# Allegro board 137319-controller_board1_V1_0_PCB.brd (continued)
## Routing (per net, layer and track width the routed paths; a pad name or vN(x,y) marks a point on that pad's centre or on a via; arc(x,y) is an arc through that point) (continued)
VBUS: length 25.2
  TOP w0.508: v2(13.82,42.04) 13.21,42.04 13.08,42.16 U10.5
  TOP w0.635: v2(9.91,48.39) 9.91,49.6 C89.1
  ART03 w0.635: J5.1 8.86,43.05 11.94,43.05 12.95,42.04 v2(13.82,42.04) v2(13.82,43.03) 13.82,44.09 13.08,44.83 10.79,44.83 9.91,45.72 v2(9.91,47.37) v2(9.91,48.39)
  BOTTOM w0.635: FB4.1 v2(9.91,47.37) v2(9.91,48.39)
VCC: length 16.2
  TOP w0.381: C2.1 v2(51.05,69.47)
  ART03 w0.381: v2(13.72,48.9) 13.72,45.47 14.73,44.45 14.73,39.75 13.34,38.35 v2(13.34,37.34)
  BOTTOM w0.508: U9.2 C90.1 v2(13.34,37.34)
  vias: v2(11.94,81.92) v2(11.94,81.15) v2(12.95,81.92) v2(12.95,81.15) v2(14.61,48.9)
VCC_1V1: length 9.4
  TOP w0.381: U2.V12 33.84,45.05 v1(34.24,44.65) ; v2(33.27,39.62) 34.16,39.62 34.54,39.24 C61.1
  BOTTOM w0.381: v1(34.24,44.65) 34.24,40.59 v2(33.27,39.62) 33.27,39.12 C62.1
VCC_2V5_SDRAM: length 18.4
  TOP w0.381: U2.E6 v1(28.64,55.85) ; v1(31.84,55.85) 32.24,55.46 U2.E10 ; U2.J5 v1(27.84,52.65) ; U2.T11 v1(33.44,46.25)
  TOP w0.508: C45.1 20.19,58.42 C47.1 v2(21.46,59.56)
  ART03 w0.381: v1(31.84,55.85) 32.64,55.06 32.64,47.05 v1(33.44,46.25)
  BOTTOM w0.381: C46.1 32.92,46.25 v1(33.44,46.25) ; v1(28.64,55.85) 28.64,55.05 C44.1 ; C59.1 32.28,55.85 v1(31.84,55.85)
VCC_3V3_ADC: length 10.2
  TOP w0.381: FB2.1 C86.1 20.45,47.37 v2(21.21,47.37) 21.88,46.7 21.88,46.06 22.89,45.05 U2.V1
  BOTTOM w0.381: C85.1 19.68,47.37 v2(21.21,47.37)
VCC_3V3_MCULDO: length 6.6
  TOP w0.381: U2.Y10 32.24,42.14 30.73,40.64 v2(30.73,39.62) C83.1
  BOTTOM w0.381: v2(30.73,39.62) C82.1
VDD12: length 25.9
  TOP w0.381: U2.M8 30.64,49.85 v1(30.24,49.45) ; v1(30.24,47.85) 30.64,48.25 U2.P8 ; v1(31.04,48.65) 31.44,49.05 U2.N9 ; U2.H12 33.84,53.05 v1(34.24,53.45) ; v1(35.04,52.65) 34.64,52.25 U2.J13 ; U2.G9 v1(31.04,54.25) ; U2.L7 29.84,50.65 v1(29.44,50.25) ; U2.K14 35.44,51.45 v1(35.84,51.85) ; U2.P12 v1(34.24,47.85) ; U2.K8 30.64,51.45 v1(30.24,51.85) ; U2.H10 v1(31.84,53.45) ; U2.P14 v1(35.84,47.85) ; v1(31.84,47.85) 32.24,48.25 U2.P10 ; U2.N13 v1(35.04,48.65) ; U2.G7 v1(29.44,54.25) ; U2.L13 34.64,50.65 v1(35.04,50.25) ; U2.N7 29.84,49.05 v1(29.44,48.65) ; U2.H14 35.44,53.05 v1(35.84,53.45) ; v1(35.04,54.25) 34.64,53.85 U2.G13 ; U2.H8 v1(30.24,53.45) ; U2.J7 v1(29.44,52.65) ; U2.N11 v1(33.44,48.65) ; U2.M14 v1(35.84,49.45) ; U2.G11 v1(33.44,54.25)
  BOTTOM w0.381: C57.1 30.24,51.42 v1(30.24,51.85) ; v1(29.44,48.65) 28.79,48.01 C53.1 ; C50.1 35.04,50.81 v1(35.04,50.25) ; C52.1 36.54,51.85 v1(35.84,51.85) ; v1(35.84,47.85) 36.08,47.61 36.08,47.57 36.19,47.46 36.23,47.46 36.45,47.24 C49.1 ; C56.1 32.27,53.45 v1(31.84,53.45) ; v1(34.24,47.85) 34.24,47.17 C55.1 ; C51.1 36.5,49.45 v1(35.84,49.45) ; v1(31.84,47.85) 32.23,47.85 C58.1 ; v2(21.09,53.21) 21.53,53.21 C48.1 21.85,52.4 v2(21.08,52.4) ; C60.1 30.86,47.29 30.3,47.85 v1(30.24,47.85) ; 36.58,53.98 36.36,53.98 v1(35.84,53.45)
VDD15: length 75.3
  TOP w0.254: v2(9.53,72.64) 10.16,73.27 U14.14
  TOP w0.381: C79.1 v2(17.08,65.09) ; U3.R1 v1(32.9,67.65) 33.24,67.31 35.56,67.31 36.32,68.07 37.63,68.07 38.73,66.97 39.88,66.97 40.17,66.67 40.17,65.3 C38.1 ; U2.E9 v1(31.04,55.85) ; U2.D5 v1(27.84,56.65) ; U3.K8 v1(28.9,73.25) ; U2.E7 v1(29.44,55.85) ; U3.D2 v1(24.11,69.25) ; U3.A1 v1(21.71,67.65) ; U2.E4 v1(27.84,55.05) U2.F5 ; U2.D11 v1(33.44,56.65) ; U3.C1 v1(23.31,67.65) ; U3.A8 v1(20.91,74.05) ; U3.E9 v1(24.9,74.05) ; U3.R9 v1(32.9,74.05) ; U2.H5 v1(27.84,53.45) ; U3.N9 v1(31.3,74.05) ; U3.F1 v1(25.71,67.65) ; U3.H2 v1(26.5,69.25) ; U3.K2 v1(28.9,69.25) ; U3.G7 v1(25.71,72.45) ; U3.D9 v1(24.11,74.05) ; U3.N1 30.9,68.05 v1(30.51,67.65) ; U2.K5 v1(27.84,51.85) ; U3.H9 v1(27.3,74.05) ; U3.C9 v1(23.31,74.05) ; U3.B2 v1(22.51,68.45)
  ART03 w0.381: v1(27.84,51.85) 28.36,52.38 28.36,52.93 v1(27.84,53.45)
  BOTTOM w0.305: C39.1 28.07,51.63 v1(27.84,51.85)
  BOTTOM w0.381: C41.1 34.02,56.65 v1(33.44,56.65) ; C16.1 20.91,74.88 v1(20.91,74.05) 20.33,74.05 20.07,73.79 ; v1(28.9,69.25) 29.56,69.25 C24.1 ; R11.1 32.51,67.25 v1(32.9,67.65) ; C42.1 C39.1 ; v1(24.9,74.05) 25.4,74.54 C18.1 ; 23.75,66.67 23.75,67.2 v1(23.31,67.65) ; C40.1 27.95,53.34 v1(27.84,53.45) ; C7.1 23.37,74.11 v1(23.31,74.05) ; v1(25.71,72.45) 25.71,71.93 C22.1 ; C43.1 30.86,55.67 v1(31.04,55.85) ; v1(24.11,69.25) 24.35,69.25 C17.1 ; C12.1 C10.1 32.9,75.07 v1(32.9,74.05) ; v2(17.08,65.09) 17.97,65.09 18.8,64.26 R8.1 C3.1 ; C8.1 21.46,67.4 v1(21.71,67.65) 21.28,68.07 C13.1 ; v2(9.53,72.64) 10.54,71.63 R87.2 11.68,69.6 12.95,68.33 14.48,68.33 15.49,67.31 v2(15.49,66.8) ; C21.1 C19.1 30.61,67.55 v1(30.51,67.65) ; C11.1 C9.1 27.3,75.06 v1(27.3,74.05) ; C14.1 24.11,74.91 v1(24.11,74.05) ; v1(28.9,73.25) 28.75,73.41 C20.1 ; v2(17.02,66.8) 17.4,67.18 17.4,70.36 R88.1
  vias: v2(14.61,66.8) v2(15.82,51.94) v2(17.01,51.94)
VDD33: length 139.2
  TOP w0.127: U2.V8 30.64,45.05 v1(30.24,44.65)
  TOP w0.254: RA4.1 46.23,55.24 46.86,54.61 v2(47.62,54.61) ; RA4.3 v2(47.62,56.26) ; RA3.1 46.74,49.66 v2(46.86,49.53) ; RA7.3 18.29,54.61 v2(17.91,54.23) 18.03,54.1 RA7.4 ; RA7.2 18.16,55.12 v2(17.91,55.37)
  TOP w0.305: v2(17.91,55.37) 18.16,55.63 RA7.1 ; 49.53,24.76 U16.20
  TOP w0.381: v1(35.84,57.45) 36.24,57.06 U2.C15 ; U11.H7 v1(31.35,18.74) ; v1(34.24,57.45) 33.84,57.05 U2.C12 ; U2.W18 38.64,44.25 v1(39.04,43.85) ; C63.1 v2(17.27,37.47) ; U4.J6 v1(43.09,69.86) ; U11.G8 v1(32.95,20.34) ; R80.1 R82.1 27.3,30.73 v2(27.18,30.86) ; v1(38.24,46.25) 37.84,46.65 U2.T17 U2.U16 ; U11.L7 v1(31.35,16.34) U11.L6 ; R54.1 v2(19.75,15.69) ; U2.C18 38.64,57.05 v1(39.04,57.45) ; U11.C7 v1(31.35,23.54) U11.C6 ; U18.5 20.77,33.21 v2(20.83,33.15) ; U11.F7 v1(31.35,21.14) ; U2.T12 33.84,46.65 v1(34.24,46.25) ; D4.2 17.72,39.05 v2(16.89,39.88) ; v1(26.24,48.65) 26.64,49.05 U2.N3 ; U11.G11 v1(34.55,20.34) ; C75.1 v2(44.83,39.62) ; v1(26.24,51.85) 26.64,51.45 U2.K3 ; U4.H8 44.29,71.06 v1(44.69,71.46) ; U11.F11 v1(34.55,21.14) ; v1(38.24,48.65) 37.84,49.05 U2.N17 ; v1(38.24,51.85) 37.84,51.45 U2.K17 ; U11.H11 v1(35.35,18.74) ; U8.4 v2(16.32,26.1) ; R47.2 v2(13.72,30.35) ; U11.C8 v1(32.95,23.54) ; U4.G4 41.09,71.86 v1(40.69,72.26) ; R53.1 v2(17.85,15.69) ; U4.D3 v1(40.69,74.66) ; U11.L8 v1(32.95,16.34) ; U11.G6 v1(30.55,20.34) ; U11.J3 v1(28.15,17.94) ; U11.G3 v1(28.15,20.34) ; R79.1 v2(26.04,30.86) ; U2.F18 38.64,54.65 v1(39.04,55.05) ; U11.F2 v1(27.35,21.14) ; R70.2 v2(45.97,14.35) ; U11.K3 v1(28.15,17.14) ; U2.V14 v1(35.84,44.65) ; U11.J11 v1(35.35,17.94) ; v2(34,30.86) 34,30.82 33.91,30.73 R81.1 ; U2.P5 v1(27.84,48.65) ; D2.2 v2(22.04,35.5) ; R27.2 v2(17.78,56.77)
  TOP w0.508: D3.2 v2(16.95,42.22) ; R85.1 v2(46.35,21.59) ; R84.1 v2(48.64,21.59) ; FB3.2 v2(17.27,46.35) ; S1.9 v2(55.56,42.29) ; FB5.2 v2(41.27,16.13) ; v2(17.27,49.65) 17.27,49.66 FB2.2 ; S1.12 v2(55.56,46.1) ; 56.67,44.83 v2(55.56,44.83) ; R48.2 v2(44.07,59.18) ; 56.67,47.37 v2(55.56,47.37) ; R49.2 v2(44.07,57.91) ; U17.5 v2(41.09,14.41) ; S1.14 v2(55.56,48.64) ; S1.10 v2(55.56,43.56) ; 56.67,49.91 v2(55.56,49.91) ; 49.53,24.76 49.66,24.64 49.66,23.5 v2(50.42,23.5) ; S1.16 v2(55.56,51.18) ; v2(8.51,21.08) 7.75,21.08 7.74,21.08 CN1.4
  BOTTOM w0.305: U15.20 14.36,62.36 v2(14.99,62.99)
  BOTTOM w0.381: v1(35.35,17.94) 35.43,17.86 C107.1 ; C100.1 28.15,19.26 v1(28.15,17.94) ; v2(47.62,56.26) 46.48,56.26 R1.2 ; v2(42.04,62.48) C76.1 C65.1 C69.1 ; C97.1 34.66,20.45 v1(34.55,20.34) ; C72.1 36.65,57.45 v1(35.84,57.45) ; C27.1 45.3,71.46 v1(44.69,71.46) ; v1(40.69,72.26) 40.69,72.44 C28.1 ; v1(39.04,43.85) 38.86,43.68 C64.1 ; R29.1 33.91,35.73 v2(33.74,35.56) ; v1(28.15,20.34) 28.72,20.34 C96.1 ; v2(16.88,22.86) 16.88,21.1 17.27,20.7 R56.1 ; v1(32.95,20.34) 32.95,19.87 C99.1 ; v1(32.95,23.54) 33.36,23.54 C106.1 ; v1(35.84,44.65) 35.43,44.25 C67.1 ; v2(17.27,46.35) 17.4,46.23 R46.1 ; v2(46.86,49.53) 45.97,50.42 R5.2 ; v1(39.04,55.05) 38.09,56.01 C71.1 ; R33.1 R35.1 ; C109.1 35.43,18.82 v1(35.35,18.74) ; C88.2 v2(8.51,21.08) ; C25.1 40.69,74.5 v1(40.69,74.66) 40.12,74.66 39.5,74.04 38.99,74.04 ; C98.1 27.76,17.53 v1(28.15,17.14) ; v2(15.75,30.48) 16.51,30.48 17.78,31.75 R50.2 ; R2.2 46.86,54.61 v2(47.62,54.61) ; v2(47.73,51.06) 47.73,51.56 47.48,51.82 46.74,51.82 R4.2 R3.2 ; v1(43.09,69.86) 42.93,69.7 C26.1 ; R58.1 v2(16.32,26.1) ; R57.1 18.8,23.94 v2(18.8,22.86) ; v1(39.04,57.45) 39.12,57.53 C66.1 ; R75.2 v2(31.37,30.86) ; C108.1 32.34,16.34 v1(32.95,16.34) ; v2(42.8,36.83) 42.04,37.59 42.04,37.72 ; v1(38.24,46.25) 39.03,45.47 C68.1 ; R71.2 42.93,11.18 43.31,10.79 v2(43.31,9.27) ; 43.31,12.32 v2(44.07,12.32) ; R55.1 v2(20.7,20.7) ; 39.75,37.72 v2(39.75,36.83) ; C36.1 v2(20.83,33.15)
  BOTTOM w0.508: v2(41.09,14.41) 41.15,14.35 C93.1 ; C74.1 C70.1 v2(40.26,76.16) ; v2(8.51,22.86) 7.75,22.86 C87.1 ; v2(17.27,49.65) 17.52,49.4 R35.1 ; C1.1 v2(14.99,62.99) ; R16.1 v2(42.55,78.87) ; C73.1 v2(41.27,76.16) ; R17.1 v2(44.2,78.87)
  vias: v2(23.88,30.86) v2(24,22.23) v2(24,21.34) v2(24.89,30.86) v2(24.94,12.7) v2(24.94,11.81) v2(56.01,59.69) v2(56.01,58.8)
AD0: length 62.8
  ART03 w0.127: v2(18.03,40.01) 18.29,39.75 18.29,32.51 21.08,29.72 21.08,27.24 22.48,25.85 22.48,12.57 v2(21.34,11.43)
  BOTTOM w0.152: R38.2 18.16,39.88 v2(18.03,40.01) ; v2(21.34,11.43) 21.34,11.3 26.04,6.6 46.4,6.6 J2.39
AD1: length 67.6
  ART03 w0.127: v2(21.34,10.29) 22.86,11.81 22.86,26 21.46,27.4 21.46,35.43 20.19,36.7 20.19,43.43 v2(21.21,44.45)
  BOTTOM w0.152: v2(21.34,10.29) 25.53,6.1 44.9,6.1 J2.37 ; R39.2 19.05,43.81 19.68,44.45 v2(21.21,44.45)
AD2: length 55.5
  ART03 w0.127: v2(21.34,9.14) 23.24,11.05 23.24,26.16 22.1,27.3 v2(22.1,33.15)
  BOTTOM w0.152: v2(21.34,9.14) 24.89,5.59 43.41,5.59 J2.35 ; v2(22.1,33.15) 21.97,33.15 21.08,34.04 R40.2
BCTRL: length 9.4
  TOP w0.127: 22.86,46.1 22.99,45.97 24.26,45.97 24.53,46.25 25.43,46.25 U2.T2
  TOP w0.152: 22.86,46.1 22.48,46.48 22.48,48.77 20.26,50.99 Q1.1
BOARD_ID0: length 10.1
  TOP w0.127: v1(36.64,46.25) 36.24,46.65 U2.T15
  BOTTOM w0.127: v1(36.64,46.25) 36.24,45.86 36.24,42.42
  BOTTOM w0.152: R29.2 R30.1 36.24,39.67 36.24,42.42
BOARD_ID1: length 11
  TOP w0.127: U2.U15 36.24,45.85 v1(36.64,45.45)
  BOTTOM w0.152: v1(36.64,45.45) 37.05,45.05 37.05,41.18 38.73,39.5 40.13,39.5 R32.1 R31.2
BOARD_ID2: length 10.3
  TOP w0.127: U2.P4 v1(27.04,48.65)
  BOTTOM w0.127: 22.86,48.51 23.12,48.25 26.64,48.25 v1(27.04,48.65)
  BOTTOM w0.152: 22.86,48.51 22.73,48.64 21.46,48.64 R33.2 R34.1
BOARD_ID3: length 8.9
  TOP w0.127: v1(26.24,47.85) 26.64,48.25 U2.P3
  BOTTOM w0.127: 22.86,47.75 23.16,47.46 25.84,47.46 v1(26.24,47.85)
  BOTTOM w0.152: R35.2 R36.1 22.35,48.26 22.86,47.75
BOOT_SEL: length 8.6
  TOP w0.127: U11.D7 v1(31.35,22.74)
  BOTTOM w0.127: v1(31.35,22.74) 31.75,23.14 31.75,26.04
  BOTTOM w0.152: R75.1 R74.2 32.64,27.56 31.75,26.67 31.75,26.04
BOOTMOD0: length 17.3
  TOP w0.127: U2.N18 38.64,49.05 v1(39.04,48.65)
  TOP w0.152: S1.1 v2(51.69,51.18) ; RA1.5 v2(44.07,48.39)
  ART04 w0.127: v2(44.07,48.39) 44.07,49.02 45.47,50.42 50.93,50.42 v2(51.69,51.18)
  BOTTOM w0.127: 41.27,49.05 41.13,49.05 41.12,49.05 39.44,49.05 v1(39.04,48.65)
  BOTTOM w0.152: v2(44.07,48.39) 43.41,49.05 41.27,49.05
BOOTMOD1: length 19.9
  TOP w0.127: U2.N16 v1(37.44,48.65)
  TOP w0.152: RA1.6 44.35,47.88 44.3,47.83 43.36,47.83 v2(42.8,48.39) ; 50.52,49.91 v2(51.69,49.91)
  ART04 w0.127: v2(42.8,48.39) 43.35,47.84 44.4,47.84 46.64,50.08 51.52,50.08 v2(51.69,49.91)
  BOTTOM w0.127: 41.27,48.25 37.84,48.25 v1(37.44,48.65)
  BOTTOM w0.152: v2(42.8,48.39) 42.67,48.25 41.27,48.25
CAN_RX: length 32.3
  TOP w0.127: U2.B14 v1(35.84,58.25)
  ART03 w0.127: v1(35.84,58.25) 35.31,58.79 35.31,59.44 35.94,60.07 35.94,65.28 36.2,65.53 36.2,77.81 J1.18
CAN_TX: length 34.8
  TOP w0.152: v2(38.43,61.59) 37.59,62.43 37.59,64.26 37.34,64.52 R26.1
  BOTTOM w0.152: J1.17 29.01,86.99 29.01,85.59 31.67,82.93 32.26,82.93 37.21,77.98 37.21,67.94 38.43,66.73 v2(38.43,61.59)
CPU_RST_N: length 23.8
  TOP w0.254: R66.1 32.13,30.48 32.13,31.62 v2(31.37,32.38) ; R51.1 C37.1 R47.1 16.85,31.24 U18.3 17.08,31.31 v2(17.91,30.48)
  ART04 w0.254: v2(31.37,32.38) 30.1,33.66 24.13,33.66 22.71,32.23 19.66,32.23 v2(17.91,30.48)
DDR_A0: length 22.5
  TOP w0.127: v1(30.24,57.45) 29.84,57.05 U2.C7 ; U3.N3 v1(30.51,70.05)
  ART03 w0.127: v1(30.51,70.05) 30.1,69.64 30.1,67.28 31.24,66.14 31.24,64.14 31.37,64.01 31.62,64.01 31.75,63.88 31.75,63.63 31.62,63.5 31.37,63.5 31.24,63.37 31.24,63.12 31.37,62.99 33.15,62.99 33.27,62.87 33.27,62.61 33.15,62.48 30.6,62.48 30.48,62.36 30.48,61.9 30.15,61.57 30.15,61.27 29.7,60.82 29.7,60.37 29.84,60.23 29.84,59.65 29.84,59.65 29.84,59.22 29.84,59.22 29.84,58.89 29.84,58.89 29.84,58.8 29.99,58.66 31.5,58.66 31.62,58.53 31.62,58.29 31.5,58.17 30.95,58.17 v1(30.24,57.45)
DDR_A1: length 20.2
  TOP w0.127: U2.C11 v1(33.44,57.45) ; U3.P7 v1(32.11,72.45)
  BOTTOM w0.127: 33.45,72.85 32.51,72.85 v1(32.11,72.45)
  BOTTOM w0.152: 33.45,72.85 35.69,70.61 35.69,64.26 33.53,62.1 33.53,59.31 33.02,58.8 33.02,57.87 v1(33.44,57.45)
DDR_A2: length 21.3
  TOP w0.127: U3.P3 v1(32.11,69.25) ; 30.86,60.2 30.86,60.07 30.64,59.85 U2.A8
  TOP w0.152: v2(31.41,61.09) 30.86,60.54 30.86,60.2
  ART03 w0.127: v1(32.11,69.25) 32.71,69.85 34.29,69.85 34.54,69.6 34.54,61.85 33.53,60.83 33.53,60.58 33.66,60.45 34.1,60.45 34.29,60.26 34.29,60.07 34.16,59.94 33.15,59.94 33.02,60.07 33.02,60.96 32.89,61.09 32.64,61.09 32.51,60.96 32.51,60.71 32.38,60.58 32.13,60.58 32,60.71 32,60.96 31.88,61.09 v2(31.41,61.09)
DDR_A3: length 20.2
  TOP w0.127: U3.N2 v1(31.3,69.25) ; U2.B7 29.44,58.25 29.44,59.02 v1(30.24,59.82)
  ART04 w0.127: v1(31.3,69.25) 31.7,68.85 31.7,67.95 32.73,66.93 33.66,66.93 33.78,66.8 33.78,64.77 33.66,64.64 32.89,64.64 32.77,64.52 32.77,64.26 32.89,64.14 33.66,64.14 33.76,64.03 33.76,63.75 33.63,63.63 32.89,63.63 32.77,63.5 32.77,63.25 32.89,63.12 33.66,63.12 33.78,62.99 33.78,62.74 33.66,62.61 32.89,62.61 32.77,62.48 32.77,60.96 32.27,60.47 30.89,60.47 v1(30.24,59.82)
DDR_A4: length 20.8
  TOP w0.127: U2.A6 29.04,59.52 v1(29.34,59.82) ; U3.P8 v1(32.11,73.25)
  ART04 w0.127: v1(29.34,59.82) 29.3,59.86 29.3,60.52 30.51,61.72 32,61.72 32.38,62.1 32.38,64.9 32.51,65.02 33.27,65.02 33.4,65.15 33.4,66.42 33.27,66.55 32.64,66.55 32.13,67.06 31.11,67.06 30.9,67.27 30.9,70.27 31.71,71.08 31.71,72.85 v1(32.11,73.25)
DDR_A5: length 21.5
  TOP w0.127: 28.7,60.2 28.63,60.13 28.63,58.26 U2.B6 ; U3.P2 v1(31.3,68.45)
  TOP w0.152: v2(30.25,60.6) 29.1,60.6 28.7,60.2
  ART03 w0.127: v1(31.3,68.45) 30.9,68.04 30.9,67.02 31.62,66.29 31.88,66.29 32,66.17 32,65.79 31.88,65.66 31.75,65.66 31.62,65.53 31.62,65.15 31.75,65.02 32.26,65.02 32.38,64.9 32.38,64.64 32.51,64.52 32.77,64.52 32.89,64.64 32.89,65.02 33.02,65.15 33.27,65.15 33.4,65.02 33.4,64.14 33.27,64.01 32.26,64.01 32.13,63.88 32.13,63.63 32.26,63.5 33.53,63.5 33.66,63.37 33.66,62.36 33.4,62.1 31.15,62.1 30.48,61.44 30.48,60.83 v2(30.25,60.6)
DDR_A6: length 20.1
  TOP w0.127: U3.R8 v1(32.9,73.25) ; U2.A9 v1(31.44,59.3)
  ART04 w0.127: v1(32.9,73.25) 34.16,71.99 34.16,62.48 33.91,62.23 33.27,62.23 33.15,62.1 33.15,61.85 33.27,61.72 33.91,61.72 34.04,61.59 34.04,61.34 33.91,61.21 33.27,61.21 33.15,61.09 33.15,59.18 32.88,58.91 31.83,58.91 v1(31.44,59.3)
DDR_A7: length 21.7
  TOP w0.127: U2.A7 29.84,58.65 v1(30.24,59.05) ; U3.R2 v1(32.11,68.45)
  ART03 w0.127: v1(30.24,59.05) 30.86,59.68 30.86,61.35 31.14,61.63 32.98,61.63 33.27,61.34 33.53,61.34 34.16,61.98 34.16,64.52 34.04,64.64 33.91,64.64 33.78,64.77 33.78,65.02 33.91,65.15 34.04,65.15 34.16,65.28 34.16,65.53 34.04,65.66 33.4,65.66 33.27,65.79 33.27,66.04 33.4,66.17 34.04,66.17 34.16,66.29 34.16,67.82 34.04,67.94 33.78,67.94 33.66,67.82 33.66,66.67 33.53,66.55 33.27,66.55 33.15,66.67 33.15,67.06 33.02,67.18 32.77,67.18 32.64,67.06 32.64,66.93 32.51,66.8 31.75,66.8 31.62,66.93 31.62,67.18 31.75,67.31 31.98,67.31 32.11,67.44 v1(32.11,68.45)
DDR_A8: length 19
  TOP w0.127: U2.A11 33.04,59.52 33.72,60.2 ; U3.T8 v1(33.71,73.25)
  TOP w0.152: 33.72,60.2 v1(34.38,60.87)
  BOTTOM w0.152: v1(34.38,60.87) 34.38,62.45 34.92,62.99 35.18,62.99 35.31,62.87 35.31,62.48 35.43,62.36 35.69,62.36 35.81,62.48 35.81,62.99 36.07,63.25 36.07,70.88 v1(33.71,73.25)
DDR_A9: length 18.5
  TOP w0.127: U3.R3 v1(32.9,69.25) ; v1(31.44,60.06) 31.03,59.66 31.03,58.26 U2.B9
  BOTTOM w0.127: 31.3,60.2 v1(31.44,60.06)
  BOTTOM w0.152: v1(32.9,69.25) 33.75,69.25 34.16,68.83 34.16,65.15 33.02,64.01 31.65,64.01 30.48,62.84 30.48,62.48 30.61,62.36 31.37,62.36 31.5,62.23 31.5,61.98 31.37,61.85 30.23,61.85 30.1,61.72 30.1,61.47 30.23,61.34 30.61,61.34 30.81,61.14 30.81,60.7 31.3,60.2
DDR_A10: length 20.4
  TOP w0.127: U3.L7 v1(29.71,72.45) ; U2.D7 v1(29.44,56.65)
  ART04 w0.127: v1(29.44,56.65) 29.04,57.05 29.04,59.55 28.92,59.67 28.92,61.69 29.71,62.48 31.5,62.48 31.62,62.61 31.62,65.41 29.3,67.72 29.3,70.47 29.71,70.87 v1(29.71,72.45)
DDR_A11: length 19.4
  TOP w0.127: U3.R7 v1(32.9,72.45) ; U2.D10 v1(31.84,56.65)
  BOTTOM w0.152: v1(31.84,56.65) 31.84,58.26 33.15,59.56 33.15,62.36 35.31,64.52 35.31,70.05 v1(32.9,72.45)
DDR_A12: length 18.9
  TOP w0.127: v1(32.26,60.07) 32.66,59.67 32.66,59.14 32.65,59.13 32.65,57.46 U2.C10 ; v1(31.3,72.45) U3.N7
  BOTTOM w0.127: 32.26,60.2 v1(32.26,60.07)
  BOTTOM w0.152: v1(31.3,72.45) 31.3,71.95 33.4,69.85 33.91,69.85 34.54,69.22 34.54,64.9 32.26,62.61 32.26,60.2
DDR_BA0: length 22.1
  TOP w0.127: U3.M2 v1(30.51,69.25) ; U2.C8 v1(31.04,57.45)
  ART03 w0.127: v1(30.51,69.25) 31.49,70.23 34.54,70.23 34.92,69.85 34.92,60.2 34.29,59.56 33.27,59.56 32.38,58.67 32.13,58.67 32,58.55 32,58.29 32.13,58.17 32.38,58.17 32.51,58.04 32.51,57.78 32.38,57.66 31.24,57.66 v1(31.04,57.45)
DDR_BA1: length 20
  TOP w0.127: v1(32.26,59.31) 31.84,58.89 31.84,57.45 U2.C9 ; U3.N8 v1(31.3,73.25)
  BOTTOM w0.127: 32.13,71.75 31.71,72.18 31.71,72.43 31.7,72.44 31.7,72.85 v1(31.3,73.25)
  BOTTOM w0.152: v1(32.26,59.31) 32.77,59.82 32.77,62.48 34.92,64.64 34.92,69.47 33.99,70.41 33.48,70.41 32.13,71.75
DDR_BA2: length 22.2
  TOP w0.127: U2.D8 v1(30.24,56.65) ; U3.M3 v1(29.71,70.05)
  ART03 w0.127: v1(30.24,56.65) 29.84,57.05 29.84,57.61 29.46,57.99 29.46,58.17 29.36,58.27 29.07,58.27 28.96,58.39 28.96,58.56 29.07,58.67 29.34,58.67 29.46,58.8 29.46,59.05 29.34,59.18 29.08,59.18 28.96,59.31 28.96,59.44 28.83,59.56 28.83,60.33 28.96,60.45 29.21,60.45 29.34,60.58 29.34,60.83 29.21,60.96 28.96,60.96 28.83,61.09 28.83,61.85 29.08,62.1 29.84,62.1 30.1,62.36 30.1,62.74 30.23,62.87 30.73,62.87 30.86,62.99 30.86,63.25 30.73,63.37 30.23,63.37 30.1,63.5 30.1,64.01 30.23,64.14 30.71,64.14 30.83,64.26 30.83,65.3 30.73,65.41 29.72,65.41 29.59,65.53 29.59,65.77 29.72,65.9 30.48,65.9 30.61,66.03 30.61,66.29 30.48,66.42 29.83,66.42 29.71,66.55 v1(29.71,70.05)
DDR_CAS_B: length 17.9
  TOP w0.127: U2.B4 v1(27.84,58.25) ; U3.K3 v1(28.11,70.05)
  BOTTOM w0.127: v1(28.11,70.05) 28.5,69.65 28.5,68.15
  BOTTOM w0.152: 28.5,68.15 29.1,67.55 29.6,67.55 30.07,67.08 30.07,63.86 28.32,62.1 27.56,62.1 27.43,61.98 27.43,61.59 27.56,61.47 27.94,61.47 28.07,61.34 28.07,61.09 27.94,60.96 27.56,60.96 27.43,60.83 27.43,60.55 27.53,60.45 27.94,60.45 28.07,60.33 28.07,60.07 27.94,59.94 27.43,59.94 27.31,59.82 27.31,58.79 v1(27.84,58.25)
DDR_CKE: length 22.1
  TOP w0.127: U3.K9 v1(28.9,74.05) ; U2.A5 28.24,60.2
  TOP w0.152: 28.24,60.2 28.24,60.24 v2(29.46,61.47)
  ART04 w0.127: v2(29.46,61.47) 30.1,62.1 31.75,62.1 32,62.36 32,66.42 31.75,66.67 30.82,66.67 29.97,67.52 29.97,69.67 30.11,69.8 30.11,70.21 30.1,70.21 30.1,73.42 29.87,73.65 29.3,73.65 v1(28.9,74.05)
  BOTTOM w0.127: R14.1 28.32,74.63 v1(28.9,74.05)
DDR_CLK: length 20.8
  TOP w0.13: U2.A2 25.84,59.42 v1(26.24,59.82) ; U3.J7 v1(28.11,72.45)
  ART04 w0.114: v1(28.11,72.45) 28.32,72.23 28.32,72.02 27.06,70.76 27.06,67.17 27.67,66.56 28.31,66.56 28.45,66.42 28.45,65.66 28.32,65.53 26.66,65.53 26.3,65.18 26.3,64.36 26.94,63.73 26.94,63.32 26.8,63.18 26.8,62.98 26.94,62.84 26.94,62.63 26.8,62.49 26.8,62.29 26.94,62.15 26.94,61.95 26.8,61.81 26.8,61.6 26.94,61.47 26.94,61.26 26.8,61.12 26.8,60.92 26.94,60.78 26.94,60.58 26.8,60.44 26.8,60.23 26.94,60.09 26.94,59.84 26.71,59.62 26.44,59.62 v1(26.24,59.82)
  BOTTOM w0.13: v1(28.11,72.45) 28.36,72.19 28.36,71.96 28,71.59 R10.1
DDR_CLK_B: length 20.9
  TOP w0.13: U2.B2 26.24,58.25 v1(26.24,59.05) ; U3.K7 v1(28.9,72.45)
  ART04 w0.114: v1(26.24,59.05) 26.44,59.25 26.87,59.25 27.3,59.69 27.3,63.88 26.67,64.52 26.67,65.02 26.81,65.16 28.47,65.16 28.82,65.51 28.82,66.57 28.46,66.93 27.83,66.93 27.43,67.32 27.43,70.61 28.69,71.87 28.69,72.23 v1(28.9,72.45)
  BOTTOM w0.13: R10.2 29.01,71.6 28.65,71.96 28.65,72.19 v1(28.9,72.45)
DDR_CS_B: length 19.3
  TOP w0.127: U2.C5 v1(27.84,57.45) ; U3.L2 v1(28.9,68.45)
  ART04 w0.127: v1(27.84,57.45) 28.32,57.94 28.32,58.17 28.45,58.29 28.57,58.29 28.7,58.42 28.7,58.67 28.57,58.8 28.45,58.8 28.32,58.93 28.32,61.85 29.34,62.87 31.11,62.87 31.24,62.99 31.24,63.25 31.11,63.37 30.73,63.37 30.61,63.5 30.61,63.88 30.73,64.01 31.11,64.01 31.24,64.14 31.24,64.39 31.11,64.52 30.1,64.52 29.97,64.64 29.97,64.9 30.1,65.02 30.86,65.02 30.99,65.15 30.99,65.41 30.86,65.53 30.19,65.53 29.97,65.75 29.97,66.55 28.9,67.62 v1(28.9,68.45)
DDR_D0: length 29.3
  TOP w0.127: U2.F4 27.44,54.65 v1(27.04,55.05) ; U3.E3 v1(24.11,70.05)
  ART03 w0.127: v1(27.04,55.05) 26.64,55.45 25.96,55.45 25.66,55.75 25.53,55.75 25.4,55.88 25.27,55.88 25.15,56.01 25.15,56.13 25.02,56.26 24.83,56.26 24.57,56.01 24.38,56.01 24.26,56.13 24.26,56.64 24.13,56.77 23.24,56.77 23.11,56.9 23.11,57.78 22.99,57.91 22.48,57.91 22.35,58.04 22.35,58.29 22.48,58.42 23.11,58.42 23.24,58.55 23.24,58.8 23.11,58.93 22.48,58.93 22.35,59.05 22.35,59.31 22.48,59.44 23.62,59.44 23.75,59.56 23.75,59.82 23.62,59.94 22.48,59.94 21.72,60.71 21.72,62.36 20.95,63.12 20.95,67.18 21.21,67.44 21.21,67.82 20.95,68.07 20.95,68.33 21.34,68.71 21.34,68.96 21.21,69.09 21.08,69.09 20.95,69.22 20.95,69.52 21.08,69.65 22.15,69.65 22.23,69.72 22.23,70.23 22.35,70.36 22.61,70.36 22.73,70.23 22.73,69.77 22.86,69.65 23.71,69.65 v1(24.11,70.05)
DDR_D1: length 29.6
  TOP w0.127: v1(26.24,53.45) 26.64,53.05 U2.H3 ; U3.F7 v1(24.9,72.45)
  ART03 w0.127: v1(26.24,53.45) 25.67,53.45 25.04,54.09 25.04,54.42 24.8,54.65 23.84,54.65 21.84,56.64 21.21,56.64 20.32,57.53 20.32,60.83 19.81,61.34 19.81,70.74 21.08,72.01 21.46,72.01 21.59,71.88 21.59,71.65 21.72,71.53 22,71.53 22.1,71.63 22.1,71.88 22.23,72.01 22.48,72.01 22.61,71.88 22.61,71.63 22.73,71.5 22.99,71.5 23.11,71.63 23.11,71.88 23.24,72.01 24.47,72.01 v1(24.9,72.45)
DDR_D2: length 29.4
  TOP w0.127: U2.D4 v1(27.04,56.65) ; U3.F2 v1(25.71,68.45)
  ART03 w0.127: v1(25.71,68.45) 26.1,68.84 26.79,68.84 26.92,68.71 26.92,66.93 26.67,66.67 26.67,66.42 26.8,66.29 27.56,66.29 27.69,66.17 27.69,65.91 27.56,65.79 27.43,65.79 27.3,65.66 27.3,65.41 27.43,65.28 27.56,65.28 27.69,65.15 27.69,64.9 27.56,64.77 27.42,64.77 27.3,64.66 27.3,64.39 27.43,64.26 27.56,64.26 27.69,64.14 27.69,63.88 27.56,63.75 27.43,63.75 27.3,63.63 27.3,63.37 27.56,63.12 27.56,62.87 27.3,62.61 27.3,62.36 27.18,62.23 26.92,62.23 26.8,62.36 26.8,62.87 26.67,62.99 26.42,62.99 26.29,62.87 26.29,62.36 26.16,62.23 25.91,62.23 25.78,62.36 25.78,62.87 25.65,62.99 25.4,62.99 25.27,62.87 25.27,61.98 25.4,61.85 27.18,61.85 27.3,61.72 27.3,61.47 27.18,61.34 27.05,61.34 26.92,61.21 26.92,60.96 27.05,60.83 27.19,60.83 27.3,60.72 27.3,59.8 27.18,59.67 27.18,58.8 27.05,58.67 26.8,58.67 26.67,58.8 26.67,60.45 26.54,60.58 25.91,60.58 25.78,60.45 25.78,58.84 26.18,58.44 26.18,58.02 26.29,57.91 26.51,57.91 26.64,57.78 26.64,57.05 v1(27.04,56.65)
DDR_D3: length 30.3
  TOP w0.127: U2.G4 v1(27.84,54.25) ; U3.F8 v1(25.71,73.25)
  ART03 w0.127: v1(27.84,54.25) 27.6,54.25 27.2,53.85 26.03,53.85 25.84,54.04 25.84,54.42 25.6,54.65 25.27,54.65 24.93,54.99 24,54.99 21.97,57.02 21.34,57.02 20.7,57.66 20.7,61.09 20.15,61.63 20.15,70.07 21.21,71.12 23.37,71.12 23.88,71.63 25.02,71.63 25.31,71.91 25.31,72.85 v1(25.71,73.25)
DDR_D4: length 29.7
  TOP w0.127: U3.H3 v1(26.51,70.05) ; U2.F3 v1(27.04,54.25)
  ART03 w0.127: v1(27.04,54.25) 27.44,54.65 27.44,57.78 27.31,57.91 27.04,57.91 26.92,58.02 26.92,58.18 27.04,58.29 27.3,58.29 27.44,58.43 27.44,59.31 27.69,59.56 27.69,62.48 28.07,62.87 28.07,66.17 28.19,66.29 28.45,66.29 28.57,66.42 28.57,66.67 28.45,66.8 28.07,66.8 27.94,66.67 27.43,66.67 27.33,66.78 27.33,67.08 27.56,67.31 27.56,67.56 27.3,67.82 27.3,68.2 27.56,68.45 27.56,68.71 27.3,68.96 27.3,69.22 27.56,69.47 27.56,70.36 27.69,70.48 28.07,70.48 28.19,70.61 28.19,70.87 28.07,70.99 27.05,70.99 26.92,71.12 26.92,71.37 27.05,71.5 27.94,71.5 28.07,71.63 28.07,71.88 27.94,72.01 27.68,72.01 27.56,72.13 27.56,72.77 27.43,72.9 27.18,72.9 27.05,72.77 27.05,72.14 26.92,72.01 26.67,72.01 26.51,71.84 v1(26.51,70.05)
DDR_D5: length 29.6
  TOP w0.127: U3.H8 26.9,73.65 v1(26.51,73.25) ; U2.J3 v1(27.04,51.85)
  ART03 w0.127: v1(27.04,51.85) 27.44,52.25 27.44,53.6 27.44,53.61 27.44,53.62 27.68,53.85 27.69,53.85 27.7,53.86 28,53.86 28.24,54.09 28.24,58.89 28.24,59.39 28.06,59.56 28.06,62.35 28.45,62.74 28.45,65.66 28.96,66.17 28.96,66.8 28.5,67.26 28.5,70.36 28.63,70.48 29.59,70.48 29.72,70.61 29.72,70.87 29.59,70.99 28.96,70.99 28.83,71.12 28.83,71.37 28.96,71.5 29.72,71.5 29.84,71.63 29.84,71.88 29.72,72.01 28.63,72.01 28.5,72.14 28.5,73.1 28.35,73.25 v1(26.51,73.25)
DDR_D6: length 29.9
  TOP w0.127: v1(26.24,56.65) 26.64,57.05 U2.C3 ; U3.G2 v1(25.71,69.25)
  ART03 w0.127: v1(25.71,69.25) 25.31,68.85 25.31,66 25.4,65.91 25.65,65.91 25.78,66.04 25.78,67.16 25.93,67.31 26.16,67.31 26.29,67.18 26.29,66.04 26.42,65.91 26.8,65.91 26.92,65.79 26.92,65.53 26.8,65.41 25.02,65.41 24.89,65.28 24.89,65.02 25.02,64.9 26.8,64.9 26.92,64.77 26.92,64.52 26.8,64.39 25.02,64.39 24.89,64.26 24.89,64.01 25.02,63.88 26.8,63.88 26.92,63.75 26.92,63.5 26.8,63.37 25.02,63.37 24.89,63.25 24.89,61.59 25.02,61.47 26.42,61.47 26.54,61.34 26.54,61.09 26.42,60.96 25.78,60.96 25.45,60.63 25.45,58.8 25.84,58.41 25.84,57.05 v1(26.24,56.65)
DDR_D7: length 29.9
  TOP w0.127: U2.G3 26.64,53.85 v1(26.24,54.25) ; U3.H7 v1(26.51,72.45)
  ART03 w0.127: v1(26.51,72.45) 26.16,72.1 26.16,70.74 26.04,70.61 25.78,70.61 25.65,70.74 25.65,71.12 25.53,71.25 25.27,71.25 25.15,71.12 25.15,70.74 25.02,70.61 24.77,70.61 24.64,70.74 24.64,71.12 24.51,71.25 24.26,71.25 24.13,71.12 24.13,70.87 24,70.74 21.46,70.74 20.57,69.85 20.57,62.99 21.34,62.23 21.34,60.33 21.46,60.2 21.76,60.2 22.01,59.95 22.01,57.45 23.96,55.5 25.56,55.5 25.84,55.22 25.84,54.93 25.84,54.93 25.84,54.89 26.24,54.49 v1(26.24,54.25)
DDR_D8: length 29.1
  TOP w0.127: U2.J1 25.04,52.25 v1(24.64,52.65)
  TOP w0.381: U3.D7 v1(23.31,72.45)
  ART04 w0.127: v1(24.64,52.65) 24.19,53.11 24.19,54.68 22.23,56.64 20.7,56.64 19.18,58.17 19.18,58.67 18.41,59.44 18.41,70.74 18.54,70.87 19.05,70.87 19.18,70.99 19.18,71.77 20.26,72.85 22.9,72.85 v1(23.31,72.45)
DDR_D9: length 28.9
  TOP w0.127: U2.D1 24.67,55.88 24,55.88 23.62,56.26 v1(23.62,57.28) ; U3.C3 v1(23.31,69.25)
  ART04 w0.127: v1(23.31,69.25) 22.91,68.85 22.91,66.76 23.24,66.42 23.24,64.9 23.37,64.77 24.89,64.77 25.02,64.64 25.02,64.39 24.89,64.26 23.37,64.26 23.24,64.14 23.24,63.88 23.37,63.75 24.89,63.75 25.02,63.63 25.02,63.37 24.89,63.25 23.75,63.25 23.62,63.12 23.62,62.87 23.75,62.74 24.89,62.74 25.02,62.61 25.02,62.36 24.89,62.23 23.75,62.23 23.62,62.1 23.62,61.85 23.75,61.72 24.89,61.72 25.02,61.59 25.02,61.34 24.89,61.21 23.75,61.21 23.62,61.09 23.62,60.83 23.75,60.71 24.89,60.71 25.02,60.58 25.02,59.56 24.89,59.44 24.26,59.44 24.13,59.31 24.13,57.78 v1(23.62,57.28)
DDR_D10: length 30.1
  TOP w0.127: U3.C8 v1(22.51,74.05) ; U2.H1 24.18,53.05 v1(23.79,52.67)
  ART04 w0.127: v1(22.51,74.05) 22.04,73.58 19.86,73.58 17.65,71.37 17.65,59.18 18.41,58.42 18.41,57.91 20.45,55.88 21.97,55.88 23.37,54.48 23.37,53.09 23.78,52.67 v1(23.79,52.67)
DDR_D11: length 29
  TOP w0.127: U2.E2 v1(25.44,55.05) ; U3.C2 v1(23.31,68.45)
  ART04 w0.127: v1(23.31,68.45) 23.7,68.84 25.14,68.84 25.27,68.71 25.27,67.94 25.02,67.69 25.02,67.44 24.77,67.18 23.88,67.18 23.75,67.06 23.75,66.29 23.88,66.17 24.64,66.17 24.77,66.29 24.77,66.67 24.89,66.8 25.15,66.8 25.27,66.67 25.27,65.79 25.15,65.66 23.75,65.66 23.62,65.53 23.62,65.28 23.75,65.15 25.27,65.15 25.4,65.02 25.4,59.18 25.27,59.05 24.64,59.05 24.51,58.93 24.51,58.67 24.64,58.55 24.77,58.55 24.89,58.42 24.89,58.17 24.77,58.04 24.64,58.04 24.51,57.91 24.51,57.66 24.64,57.53 24.77,57.53 24.89,57.4 24.89,57.02 24.77,56.9 23.88,56.9 23.75,56.77 23.75,56.52 23.88,56.39 24.13,56.39 24.26,56.26 24.26,55.88 24.38,55.75 24.64,55.75 24.77,55.88 24.77,56.39 24.89,56.52 25.31,56.52 25.44,56.39 v1(25.44,55.05)
DDR_D12: length 29.4
  TOP w0.127: U2.G1 25.04,53.85 v1(24.64,54.25) ; U3.A7 v1(20.91,72.45)
  ART04 w0.127: v1(20.91,72.45) 20.91,71.6 20.55,71.25 19.81,71.25 19.56,70.99 19.56,70.61 19.43,70.48 18.92,70.48 18.8,70.36 18.8,70.1 18.92,69.98 19.56,69.98 19.68,69.85 19.68,69.6 19.56,69.47 18.92,69.47 18.8,69.34 18.8,69.09 18.92,68.96 19.56,68.96 19.68,68.83 19.68,68.58 19.56,68.45 18.92,68.45 18.8,68.33 18.8,68.07 18.92,67.94 19.43,67.94 19.56,67.82 19.56,67.56 19.43,67.44 18.89,67.44 18.8,67.34 18.8,60.58 18.92,60.45 19.3,60.45 19.43,60.33 19.43,60.07 19.3,59.94 18.92,59.94 18.8,59.82 18.8,59.56 19.56,58.8 19.56,58.29 20.83,57.02 22.35,57.02 24.64,54.74 v1(24.64,54.25)
DDR_D13: length 29.4
  TOP w0.127: U3.A2 v1(21.71,68.45)
  TOP w0.152: v1(23.64,58.8) 22.23,58.8 22.1,58.93 22.1,59.56 22.23,59.69 22.99,59.69 23.11,59.82 23.11,60.07 22.99,60.2 22.23,60.2 22.1,60.33 22.1,60.58 22.23,60.71 23.37,60.71 23.5,60.58 23.5,59.82 23.62,59.69 23.88,59.69 24,59.82 24,60.58 24.13,60.71 24.38,60.71 24.51,60.58 24.51,59.82 24.64,59.69 24.89,59.69 25.02,59.82 25.02,60.58 25.15,60.71 25.4,60.71 25.53,60.58 25.53,59.44 25.4,59.31 24.89,59.31 24.63,59.05 24.63,57.46 U2.C1
  ART04 w0.127: v1(23.64,58.8) 23.64,59.69 23.77,59.82 24.51,59.82 24.64,59.94 24.64,60.2 24.51,60.33 23.5,60.33 23.24,60.58 23.24,62.74 22.86,63.12 22.86,66.17 22.48,66.55 22.23,66.55 22.1,66.67 22.1,67.3 22.11,67.31 22.11,68.05 v1(21.71,68.45)
DDR_D14: length 29.2
  TOP w0.127: U3.B8 v1(22.51,73.25) ; U2.H2 25.44,53.45 v1(23.79,53.45)
  ART04 w0.127: v1(22.51,73.25) 20.03,73.25 18.03,71.25 18.03,59.31 18.8,58.55 18.8,58.04 20.57,56.26 22.1,56.26 23.79,54.57 v1(23.79,53.45)
DDR_D15: length 29.5
  TOP w0.127: U3.A3 v1(21.71,69.25) ; v1(23.6,57.94) 24.1,57.94 24.26,57.78 24.26,57.15 24,56.9 24,56.39 24.13,56.26 24.38,56.26 24.51,56.39 24.51,56.52 24.66,56.66 25.43,56.66 U2.D2
  ART04 w0.127: v1(21.71,69.25) 21.21,68.75 21.21,66.29 21.34,66.17 22.23,66.17 22.48,65.91 22.48,63.37 22.35,63.25 20.57,63.25 20.45,63.12 20.45,62.74 20.57,62.61 22.73,62.61 22.86,62.48 22.86,62.23 22.73,62.1 21.59,62.1 21.46,61.98 21.46,61.72 21.59,61.59 22.73,61.59 22.86,61.47 22.86,61.21 22.73,61.09 21.59,61.09 21.46,60.96 21.46,60.33 21.59,60.2 21.84,60.2 21.97,60.33 21.97,60.58 22.1,60.71 22.73,60.71 22.86,60.58 22.86,60.33 22.73,60.2 22.48,60.2 22.35,60.07 22.35,59.82 22.48,59.69 22.73,59.69 22.86,59.56 22.86,59.31 22.73,59.18 22.48,59.18 22.35,59.05 22.35,58.8 22.48,58.67 22.86,58.67 v1(23.6,57.94)
DDR_DQM0: length 30.3
  TOP w0.127: v1(27.04,52.65) 27.44,52.25 U2.J4 ; U3.E7 v1(24.11,72.45)
  ART03 w0.127: v1(24.11,72.45) 23.71,72.84 21.07,72.84 21.07,72.84 20.01,72.84 19.43,72.26 19.43,61.21 19.94,60.71 19.94,57.4 21.08,56.26 21.72,56.26 24.92,53.05 26.64,53.05 v1(27.04,52.65)
DDR_DQM1: length 29.2
  TOP w0.127: U3.D3 23.7,69.65 v1(23.31,70.05) ; U2.G2 v1(25.44,54.25)
  ART04 w0.127: v1(23.31,70.05) 22.86,70.49 22.86,71.63 22.99,71.75 24,71.75 24.13,71.63 24.13,70.74 24.26,70.61 24.51,70.61 24.64,70.74 24.64,71.63 24.77,71.75 25.02,71.75 25.15,71.63 25.15,70.74 25.27,70.61 25.53,70.61 25.65,70.74 25.65,71.63 25.78,71.75 25.98,71.75 26.11,71.63 26.11,66.93 25.84,66.66 25.84,58.67 25.97,58.55 26.54,58.55 26.67,58.42 26.67,58.17 26.54,58.04 25.97,58.04 25.84,57.91 25.84,54.65 v1(25.44,54.25)
DDR_DQS0: length 29.7
  TOP w0.13: U2.D3 26.64,56.25 v1(26.24,55.85) ; U3.F3 v1(24.91,70.05)
  ART03 w0.114: v1(24.91,70.05) 24.91,70.04 24.91,69.62 24.51,69.23 24.51,66.29 24.38,66.17 23.75,66.17 23.62,66.29 23.62,66.81 23.27,67.17 21.95,67.17 21.6,66.83 21.6,63.47 21.95,63.13 22.76,63.13 23.1,63.47 23.1,64.76 23.24,64.9 23.75,64.9 23.88,64.77 23.88,62.61 23.75,62.48 22.58,62.48 22.24,62.14 22.24,60.93 22.58,60.59 24.4,60.59 24.52,60.46 24.52,59.49 24.36,59.32 24.36,59.14 24.52,58.98 24.52,58.8 24.36,58.64 24.36,58.46 24.52,58.29 24.52,58.11 24.36,57.95 24.36,57.77 24.52,57.61 24.52,57.3 25.92,55.9 26.2,55.9 v1(26.24,55.85)
DDR_DQS0_B: length 29.9
  TOP w0.13: U3.G3 v1(25.71,70.05) ; U2.E3 v1(27.04,55.85)
  ART03 w0.114: v1(27.04,55.85) 26.63,56.26 26.08,56.26 24.89,57.45 24.89,60.62 24.55,60.96 22.73,60.96 22.61,61.09 22.61,61.99 22.73,62.12 23.9,62.12 24.24,62.46 24.24,64.92 23.9,65.27 23.09,65.27 22.73,64.91 22.73,63.63 22.61,63.5 22.1,63.5 21.97,63.63 21.97,66.67 22.1,66.8 23.11,66.8 23.25,66.66 23.25,66.14 23.6,65.8 24.54,65.8 24.88,66.14 24.88,69.08 25.27,69.47 25.27,69.61 v1(25.71,70.05)
DDR_DQS1: length 29.5
  TOP w0.13: v2(21.46,58.76) 21.87,58.36 22.12,58.36 22.54,57.93 22.54,57.52 22.65,57.41 22.75,57.41 22.86,57.29 22.86,57.13 22.75,57.02 22.65,57.02 22.54,56.91 22.54,56.47 22.99,56.02 22.99,54.61 23.22,54.38 23.57,54.38 23.72,54.53 23.72,54.85 24.06,55.19 24.78,55.19 U2.E1 ; U3.C7 v1(22.51,72.45)
  ART04 w0.114: v2(21.46,58.76) 21.1,58.4 20.86,58.4 20.57,58.69 20.57,59.69 20.83,59.94 20.83,60.83 20.45,61.21 19.94,61.21 19.81,61.34 19.81,63.77 19.94,63.89 21.49,63.89 21.83,64.24 21.83,65.06 21.49,65.41 19.94,65.41 19.81,65.53 19.81,66.55 19.94,66.67 20.32,66.67 20.7,67.06 20.7,68.91 20.9,69.11 20.9,69.49 20.7,69.7 20.7,69.98 21.6,70.88 21.86,70.88 22.12,71.14 22.12,71.39 22.29,71.57 22.29,72.23 v1(22.51,72.45)
DDR_DQS1_B: length 29.5
  TOP w0.13: v2(21.46,57.67) 21.87,58.08 22,58.08 22.26,57.82 22.26,56.36 22.71,55.91 22.71,54.49 23.1,54.1 23.69,54.1 24,54.41 24,54.74 24.18,54.91 24.78,54.91 U2.F1 ; U3.B7 v1(21.71,72.45)
  ART04 w0.114: v1(21.71,72.45) 21.92,72.23 21.92,71.72 20.33,70.13 20.33,67.21 20.17,67.04 19.79,67.04 19.44,66.7 19.44,65.38 19.79,65.04 21.34,65.04 21.46,64.91 21.46,64.39 21.34,64.26 19.79,64.26 19.44,63.92 19.44,61.19 19.79,60.85 20.29,60.85 20.46,60.68 20.46,60.1 20.21,59.84 20.21,58.53 20.71,58.03 21.1,58.03 v2(21.46,57.67)
DDR_ODT0: length 14.3
  TOP w0.127: U3.K1 28.5,68.05 v1(28.11,67.65) ; U2.C4 v1(27.04,57.45)
  BOTTOM w0.152: v1(28.11,67.65) 28.57,67.18 29.34,67.18 29.72,66.8 29.72,64.26 27.94,62.48 27.05,62.48 26.8,62.23 26.8,57.7 v1(27.04,57.45)
DDR_RAS_B: length 19
  TOP w0.127: U3.J3 v1(28.11,69.25) ; U2.A4 v1(27.84,59.05)
  ART04 w0.127: v1(27.84,59.05) 27.84,62.36 27.97,62.48 28.32,62.48 28.45,62.61 28.45,62.87 28.32,62.99 27.94,62.99 27.84,63.09 27.84,63.37 27.97,63.5 30.1,63.5 30.23,63.63 30.23,63.88 30.1,64.01 27.94,64.01 27.81,64.14 27.81,64.39 27.94,64.52 29.46,64.52 29.59,64.64 29.59,66.42 28.5,67.51 28.5,68.85 v1(28.11,69.25)
DDR_RESET: length 18
  TOP w0.305: U3.T2 v1(33.71,68.45) ; U2.D6 v1(28.64,56.65)
  BOTTOM w0.127: 28.57,58.17 28.24,57.83 28.24,57.06 v1(28.64,56.65) 29.04,57.06 29.04,57.7 28.57,58.17
  BOTTOM w0.381: 28.57,58.17 28.57,61.59 31.5,64.52 32.77,64.52 33.53,65.28 R11.2 33.53,68.27 v1(33.71,68.45)
DDR_WE_B: length 21.3
  TOP w0.127: U3.L3 v1(28.91,70.05) ; U2.C6 v1(29.44,57.45)
  ART03 w0.127: v1(28.91,70.05) 29.34,69.62 29.34,68.07 29.21,67.94 28.96,67.94 28.83,67.82 28.83,67.56 28.96,67.44 29.21,67.44 29.34,67.31 29.34,66.04 28.83,65.53 28.83,65.15 28.96,65.02 30.23,65.02 30.35,64.9 30.35,64.64 30.23,64.52 28.96,64.52 28.83,64.39 28.83,64.14 28.96,64.01 29.59,64.01 29.72,63.88 29.72,63.63 29.59,63.5 28.96,63.5 28.83,63.37 28.83,63.12 28.96,62.99 29.59,62.99 29.72,62.87 29.72,62.61 29.59,62.48 28.7,62.48 28.45,62.23 28.45,59.56 28.57,59.44 28.57,58.32 v1(29.44,57.45)
DDR_ZQ_M: length 8.9
  TOP w0.127: U2.A3 26.64,60.2
  TOP w0.152: R12.1 25.78,61.21 26.64,60.36 26.64,60.2
DDR_ZQ_S: length 2.8
  TOP w0.127: U3.L8 v1(29.71,73.25)
  BOTTOM w0.127: v1(29.71,73.25) U3.L8 29.3,74.9 R13.1
EXTAL_MAIN: length 9.2
  TOP w0.152: U2.Y13 34.64,41.18 36.2,39.62 C31.1 36.63,38.73 36.75,38.61 36.75,35.78 Y1.1
FPGA_CLK: length 12.8
  TOP w0.127: U11.H6 v1(30.55,18.74)
  TOP w0.152: v2(41.02,17.27) R68.1
  BOTTOM w0.127: 37.59,18.34 30.95,18.34 v1(30.55,18.74)
  BOTTOM w0.152: 37.59,18.34 39.96,18.34 v2(41.02,17.27)
FPGA_RST_N: length 33
  TOP w0.127: U11.F9 v1(32.95,21.14) ; U11.N2 v1(27.35,15.54)
  TOP w0.152: U17.4 v2(42.99,14.41)
  ART03 w0.127: v1(27.35,15.54) 27.35,18.97 28.32,19.94 31.75,19.94 v1(32.95,21.14)
  BOTTOM w0.152: v1(27.35,15.54) 27.35,14.18 28.19,13.34 37.72,13.34 39.5,15.11 42.29,15.11 v2(42.99,14.41) 43.31,14.09 R69.2 C92.1
I2C_SCL_BARAMETRIC: length 20.8
  TOP w0.127: v1(35.04,57.45) 35.44,57.06 U2.C14
  TOP w0.152: R49.1 46.61,57.91 46.89,58.2 v2(47.52,58.2) U5.8
  ART04 w0.127: v2(47.52,58.2) 48.13,58.81 48.13,59.69 47.12,60.71 36.7,60.71 35.44,59.44 35.44,57.85 v1(35.04,57.45)
I2C_SDA_BARAMETRIC: length 15.8
  TOP w0.127: U2.A15 36.24,58.66 v1(35.84,59.05)
  TOP w0.152: U5.7 v2(47.52,59.45) 47.25,59.18 R48.1
  ART04 w0.127: v1(35.84,59.05) 37.11,60.33 46.64,60.33 v2(47.52,59.45)
ID0: length 49
  TOP w0.127: U2.L2 25.45,50.26 23.15,50.26 22.86,50.55
  TOP w0.152: 22.86,50.55 22.1,51.31 22.1,55.63 20.95,56.77 R27.1 19.81,57.15 19.56,57.4 16.89,57.4 v2(16.26,56.77)
  ART03 w0.127: v2(16.26,56.77) 15.62,57.4 15.62,65.66 16.04,66.08 16.04,71.67 16.89,72.52 16.89,75.06 18.98,77.14 18.98,86.98 J1.9
ID1: length 46.9
  TOP w0.127: v1(24.64,49.45) 25.04,49.85 U2.M1
  TOP w0.152: RA7.5 20.45,54.1 v2(20.57,53.98)
  ART03 w0.127: v2(20.57,53.98) 20.19,53.98 18.25,55.92 17.49,55.92 16.89,56.52 16.89,57.02 16,57.91 16,65.53 16.38,65.91 16.38,71.5 17.27,72.39 17.27,74.8 21.08,78.61 21.08,84.92 J1.10
  ART04 w0.127: v1(24.64,49.45) 23.45,49.45 22.1,50.8 22.1,54.23 21.81,54.52 21.12,54.52 v2(20.57,53.98)
ID3: length 47
  TOP w0.127: v1(24.64,48.65) 25.04,49.05 U2.N1
  TOP w0.152: RA7.6 20.29,54.61 20.34,54.56 20.88,54.56 v2(21.46,53.98)
  ART03 w0.127: v2(21.46,53.98) 20.87,54.57 20.1,54.57 18.33,56.35 18.33,57 18.01,57.32 17.23,57.32 16.38,58.17 16.38,65.28 17.65,66.55 17.65,74.61 21.46,78.42 21.46,85.46 J1.12
  ART04 w0.127: v2(21.46,53.98) 21.72,53.72 21.72,50.67 23.74,48.65 v1(24.64,48.65)
ID4: length 48.9
  TOP w0.127: v1(25.44,48.65) 25.84,49.05 U2.N2
  TOP w0.152: RA7.7 v2(20.57,55.12)
  ART03 w0.127: J1.13 23.02,87.02 23.02,85.63 21.84,84.45 21.84,78.26 18.03,74.45 18.03,65.28 17.65,64.9 17.65,58.93 18.67,57.91 18.67,56.64 20.19,55.12 v2(20.57,55.12)
  ART04 w0.127: v2(20.57,55.12) 19.94,54.48 19.94,51.94 23.63,48.25 25.04,48.25 v1(25.44,48.65)
ID5: length 47.5
  TOP w0.127: v1(27.04,49.45) 27.44,49.05 U2.N4
  TOP w0.152: v2(21.46,55.12) 20.89,55.68 20.34,55.68 20.29,55.63 RA7.8
  ART03 w0.127: J1.14 22.23,84.23 22.23,78.11 18.41,74.3 18.41,64.9 18.03,64.52 18.03,59.18 19.05,58.17 19.05,56.77 20.15,55.66 20.8,55.66 21.35,55.12 v2(21.46,55.12)
  ART04 w0.127: v1(27.04,49.45) 26.64,49.85 23.81,49.85 22.48,51.18 22.48,54.32 21.68,55.12 v2(21.46,55.12)
JTAG_TCK: length 16.5
  TOP w0.152: J6.1 56.26,31.37 56.26,29.46 55.5,28.7 52.45,28.7 51.69,27.94 48.9,27.94 47.58,26.63 U16.17 47.58,23.58 47.5,23.5
JTAG_TDI: length 14.5
  TOP w0.152: J6.9 53.34,20.57 47.37,20.57 46.91,21.03 46.91,23.37 46.79,23.5 46.35,23.5 46.35,24 46.93,24.58 U16.16
JTAG_TDO: length 10.8
  TOP w0.152: U16.5 46.93,32.71 47.24,33.02 52.07,33.02 J6.3
JTAG_TMS: length 10.5
  TOP w0.152: 48.64,23.5 48.23,23.9 U16.18 48.23,26.52 49.15,27.43 J6.5
JTCLK: length 36
  TOP w0.127: U2.K4 27.04,51.05 24.64,51.05 v1(23.84,51.85)
  ART03 w0.127: J3.4 10.29,67.56 10.29,65.53 14.35,61.47 14.35,56.9 17.78,53.47 18.41,53.47 20.57,51.31 23.29,51.31 v1(23.84,51.85)
JTDI: length 33.1
  TOP w0.127: U2.K2 v1(25.44,51.85)
  ART03 w0.127: J3.8 6.86,65.91 6.86,63.37 8.38,61.85 10.79,61.85 11.94,60.71 11.94,58.55 12.45,58.04 12.45,55.75 15.11,53.09 17.14,53.09 18.03,52.2 18.03,51.69 19.18,50.55 24.13,50.55 v1(25.44,51.85)
JTDO: length 34
  TOP w0.127: v1(24.64,51.85) 25.04,51.45 U2.K1
  ART03 w0.127: J3.6 7.62,67.69 7.62,63.25 8.64,62.23 11.05,62.23 12.32,60.96 12.32,58.67 12.95,58.04 12.95,56.13 15.62,53.47 17.27,53.47 18.41,52.32 18.41,51.82 19.3,50.93 23.71,50.93 v1(24.64,51.85)
JTMS: length 35.4
  TOP w0.127: U2.L1 24.19,50.65 v1(22.99,51.85)
  ART03 w0.127: J3.2 4.95,75.06 13.46,66.55 13.46,63.5 15.24,61.72 15.24,56.9 17.31,54.83 18.07,54.83 18.12,54.78 18.25,54.78 20.32,52.7 20.32,52.32 20.79,51.85 v1(22.99,51.85)
NF_ALE: length 22.9
  TOP w0.127: U2.E16 36.64,55.85 v1(36.64,56.65) ; U4.C4 41.09,75.06 v1(40.69,75.46)
  ART03 w0.127: v1(40.69,75.46) 39.78,74.55 38.99,74.55 36.96,72.52 36.96,65.15 36.64,64.83 v1(36.64,56.65)
NF_CE_N: length 84
  TOP w0.127: U4.C6 42.69,75.06 43.09,74.66 v1(43.09,73.86) ; v1(38.24,59.05) 38.24,58.25 37.84,57.85 U2.B17
  ART03 w0.127: v1(43.09,73.86) 42.25,73.03 40.01,73.03 38.48,71.5 38.48,64.52 39.12,63.88 39.12,60.33 38.73,59.94 38.73,59.55 v1(38.24,59.05)
  ART04 w0.127: v1(43.09,73.86) 43.09,76.42 42.23,77.28 38.16,77.28 36.32,79.12 13.21,79.12 11.18,77.09 11.18,66.8 11.94,66.04 11.94,64.26 13.6,62.6 13.6,59.68 14.26,59.02 14.26,57.95 v2(13.71,57.39)
  BOTTOM w0.152: U15.2 v2(13.71,57.39) ; v1(43.09,73.86) 43.09,75.53 42.55,76.07 R16.2
NF_CLE: length 23.6
  TOP w0.127: U2.E15 35.84,55.85 v1(35.84,55.85) ; U4.D5 v1(41.49,74.66)
  ART03 w0.127: v1(35.84,55.85) 36.42,55.85 37.04,56.48 37.04,58.42 37.04,64.6 37.34,64.9 37.34,72.26 39.24,74.17 41,74.17 v1(41.49,74.66)
NF_IO0: length 15.9
  TOP w0.127: v1(40.64,56.65) 40.24,56.25 U2.D20 ; v1(41.49,69.86) 41.49,70.66 41.09,71.06 U4.H4
  ART03 w0.127: v1(40.64,56.65) 41.04,57.05 41.04,63.63 41.4,63.99 41.4,67.7 42.04,68.34 42.04,69.32 v1(41.49,69.86)
NF_IO1: length 18.6
  TOP w0.127: v1(40.64,55.85) 40.24,55.45 U2.E20 ; U4.J4 v1(40.69,70.66)
  ART03 w0.127: v1(40.64,55.85) 40.99,55.85 41.78,56.64 41.78,59.56 42.91,60.69 42.91,67.95 42.8,68.07 42.8,69.59 41.73,70.66 v1(40.69,70.66)
NF_IO2: length 15.2
  TOP w0.127: U4.K4 v1(40.69,69.06) ; v1(39.04,55.85) 38.64,55.45
  TOP w0.381: 38.64,55.45 U2.E18
  ART03 w0.127: v1(40.69,69.06) 40.39,68.76 40.39,67.56 40.64,67.31 40.64,64.22 40.26,63.84 40.26,59.94 39.88,59.56 39.88,59.05 39.44,58.62 39.44,56.49 39.04,56.09 v1(39.04,55.85)
NF_IO3: length 18.3
  TOP w0.127: v1(37.44,55.05) 37.04,54.65 U2.F16 ; U4.K5 v1(41.49,69.06)
  ART03 w0.127: v1(41.49,69.06) 41.09,69.46 40.26,69.46 40.01,69.21 40.01,67.44 40.26,67.18 40.26,64.39 39.88,64.01 39.88,60.07 39.5,59.69 39.5,59.18 38.64,58.33 38.64,56.25 v1(37.44,55.05)
NF_IO4: length 17.7
  TOP w0.127: v1(38.24,55.05) 37.84,54.65 U2.F17
  TOP w0.152: v2(41.02,68.33) 41.55,68.33 U4.K6
  ART03 w0.127: v1(38.24,55.05) 38.64,55.45 39.21,55.45 39.44,55.69 39.44,55.95 39.44,55.95 39.44,56.02 39.68,56.25 40.01,56.25 40.24,56.49 40.24,59.29 40.64,59.69 40.64,63.75 41.02,64.14 v2(41.02,68.33)
NF_IO5: length 18.1
  TOP w0.127: v1(39.84,55.05) 39.44,54.65 U2.F19 ; U4.J7 v1(43.89,69.86)
  ART03 w0.127: v1(39.84,55.05) 40.08,55.05 40.48,55.45 40.59,55.45 41.1,55.45 42.16,56.52 42.16,59.44 43.31,60.58 43.31,69.28 v1(43.89,69.86)
NF_IO6: length 16.8
  TOP w0.127: U2.F20 40.24,54.65 v1(40.64,55.05) ; U4.K7 v1(43.89,69.06)
  ART03 w0.127: v1(43.89,69.06) 43.89,60.02 43.43,59.56 43.43,57.32 41.17,55.05 v1(40.64,55.05)
NF_IO7: length 21
  TOP w0.127: U4.J8 v1(44.69,69.86) ; v1(40.64,54.25) 40.24,53.85 U2.G20
  ART03 w0.127: v1(40.64,54.25) 41.81,54.25 42.16,54.61 44.45,54.61 44.96,55.12 44.96,65.79 45.34,66.17 45.34,69.22 v1(44.69,69.86)
NF_IO8: length 25.7
  TOP w0.127: v1(39.89,71.46) 40.29,71.06 U4.H3 ; U2.G19 39.44,53.85 v1(39.84,54.25)
  ART03 w0.127: v1(39.84,54.25) 40.24,54.65 41.32,54.65 42.55,55.88 44.32,55.88 44.62,56.17 44.62,59.75 44.29,60.07 44.29,70.03 44.06,70.26 42.77,70.26 41.97,71.06 40.29,71.06 v1(39.89,71.46)
NF_IO9: length 21.3
  TOP w0.127: U2.G18 38.64,53.85 v1(39.04,54.25) ; U4.J3 v1(39.89,70.66)
  ART03 w0.127: v1(39.04,54.25) 39.44,54.65 39.44,55.22 39.68,55.45 39.96,55.45 40.01,55.45 40.24,55.69 40.24,55.73 40.24,55.74 40.24,56.02 40.48,56.25 40.51,56.25 40.81,56.25 41.4,56.85 41.4,63.37 42.58,64.55 42.58,67.82 42.42,67.98 42.42,69.5 41.66,70.26 40.29,70.26 v1(39.89,70.66)
NF_IO10: length 22.7
  TOP w0.127: U2.G16 37.04,53.85 v1(37.44,54.25) ; U4.H5 v1(41.49,71.46)
  ART03 w0.127: v1(37.44,54.25) 36.96,54.74 36.96,55.37 37.84,56.26 37.84,57.02 38.23,57.4 38.23,58.42 39.12,59.31 39.12,59.82 39.5,60.2 39.5,64.14 38.86,64.77 38.86,71.25 39.48,71.86 41.09,71.86 v1(41.49,71.46)
NF_IO11: length 39.2
  TOP w0.127: U4.J5 42.29,70.66 v1(42.29,71.46) ; v1(37.44,53.45) 37.04,53.05 U2.H16
  ART03 w0.127: v1(42.29,71.46) 43.49,72.66 45.57,72.66 47.24,70.99 47.24,65.15 46.86,64.77 46.86,52.45 44.58,50.16 41.53,50.16 40.24,51.46 40.24,52.02 40.01,52.25 38.08,52.25 37.84,52.49 37.84,53.05 v1(37.44,53.45)
NF_IO12: length 27.4
  TOP w0.127: U4.H6 v1(43.09,70.66) ; U2.H17 37.84,53.05 v1(38.24,53.45)
  ART03 w0.127: v1(43.09,70.66) 44.13,70.66 44.53,70.26 45.06,70.26 45.72,69.61 45.72,66.04 45.34,65.66 45.34,54 44.68,53.34 38.35,53.34 v1(38.24,53.45)
NF_IO13: length 30.6
  TOP w0.127: U2.H18 38.64,53.05 39.04,53.45 39.62,53.45 39.84,53.24 v1(39.84,52.65) ; U4.G6 v1(43.09,71.46)
  ART03 w0.127: v1(39.84,52.65) 40.08,52.65 40.48,52.26 40.96,52.26 41.4,51.82 44.32,51.82 46.1,53.59 46.1,65.15 46.48,65.53 46.48,70.1 45.52,71.06 43.49,71.06 v1(43.09,71.46)
NF_IO14: length 25.4
  TOP w0.127: U2.H20 40.25,53.05 v1(40.65,52.65) ; v1(44.69,70.66) 43.89,70.66 U4.H7
  ART03 w0.127: v1(40.65,52.65) 41.6,52.65 41.91,52.96 44.84,52.96 45.72,53.85 45.72,65.41 46.1,65.79 46.1,69.76 45.19,70.66 v1(44.69,70.66)
NF_IO15: length 30.5
  TOP w0.127: U2.J20 40.24,52.25 v1(40.64,51.85) ; U4.G7 v1(43.89,71.46)
  ART03 w0.127: v1(40.64,51.85) 40.64,51.56 41.66,50.55 44.32,50.55 46.48,52.7 46.48,65.02 46.86,65.41 46.86,70.84 45.82,71.88 44.31,71.88 v1(43.89,71.46)
NF_RB_N: length 26.8
  TOP w0.127: U2.D16 v1(37.44,56.65) ; U4.C8 v1(44.69,74.66)
  ART03 w0.127: v1(37.44,56.65) 37.44,57.51 37.84,57.9 37.84,64.13 38.1,64.39 38.1,71.75 39.75,73.41 42.07,73.41 42.93,74.27 44.29,74.27 v1(44.69,74.66)
  BOTTOM w0.152: v1(44.69,74.66) 44.2,75.16 R17.2
NF_RE_N: length 70.9
  TOP w0.127: 39.62,73.86 40.69,73.86 U4.D4 ; U2.U8 30.64,45.85 v1(30.24,46.25)
  TOP w0.152: 39.62,73.86 35.51,73.86 v2(34.92,73.28)
  ART03 w0.127: v1(30.24,46.25) 30.24,46.47 28.24,48.46 28.24,50.6 28.83,51.18 30.23,51.18 30.64,51.59 30.64,56.42 31.37,57.15 32.64,57.15 32.89,57.4 32.89,58.29 33.26,58.66 34.92,58.66 35.05,58.78 35.05,59.86 35.26,60.06 35.26,60.07 35.38,60.2 35.43,60.2 35.56,60.33 35.56,72.64 v2(34.92,73.28)
  ART04 w0.127: v1(30.24,46.25) 29.84,45.85 24.55,45.85 24.38,45.68 19.22,45.68 17.53,47.37 17.53,48.01 14.22,51.31 14.22,52.83 13.08,53.98 13.08,57.91 v2(13.72,58.55)
  BOTTOM w0.152: v2(13.72,58.55) 13.06,57.89 U15.3
NF_WE_N: length 22.3
  TOP w0.127: v1(37.44,59.82) 38.24,59.82 38.64,59.42 38.64,58.66 U2.A18 ; U4.C7 v1(43.89,74.66)
  ART03 w0.127: v1(43.89,74.66) 42.86,74.66 41.98,73.79 39.5,73.79 37.72,72.01 37.72,64.64 37.44,64.36 v1(37.44,59.82)
PTA20: length 6
  TOP w0.127: 39.5,60.2 39.5,60.07 39.04,59.61 39.04,58.25 38.64,57.85 U2.B18
  TOP w0.152: R24.2 39.5,60.2
PTA30: length 27.5
  TOP w0.127: v1(38.24,47.85) 37.84,48.25 U2.P17 ; v1(32.55,25.53) 32.14,25.12 32.14,24.33 U11.B7
  ART03 w0.127: v1(38.24,47.85) 38.64,47.46 38.64,43.62 35.43,40.42 35.43,34.16 34.54,33.27 34.54,29.84 33.02,28.32 33.02,26 v1(32.55,25.53)
PTA31: length 30
  TOP w0.127: U11.E8 v1(32.95,21.94) ; U2.P16 v1(37.44,47.85)
  ART03 w0.127: v1(32.95,21.94) 32,22.89 32,25.65 32.64,26.29 32.64,28.57 33.36,29.3 33.36,32.73 35.05,34.42 35.05,40.58 37.84,43.36 37.84,47.46 v1(37.44,47.85)
PTB0: length 23.4
  TOP w0.127: v1(28.64,46.25) 29.04,46.65 U2.T6 ; U11.A2 v1(27.35,25.14)
  ART03 w0.127: v1(27.35,25.14) 27.35,27.35 27.81,27.81 27.81,31.5 27.43,31.88 27.43,34.97 27.48,35.02 27.48,35.85 27.9,36.27 27.9,41.27 29.04,42.42 29.04,45.85 v1(28.64,46.25)
PTB3: length 22.5
  TOP w0.127: U2.W7 29.84,44.25 v1(29.44,43.85) ; 30.15,26.04 U11.A5
  TOP w0.152: v2(28.33,26.79) 29.39,26.79 30.15,26.04
  ART03 w0.127: v1(29.44,43.85) 29.84,43.45 29.84,42.03 28.7,40.89 28.7,36.96 29.46,36.2 29.46,34.04 28.55,33.12 28.55,27.58 28.33,27.35 v2(28.33,26.79)
PTB4: length 21.4
  TOP w0.127: v1(29.44,43.05) 29.84,43.45 U2.Y7 ; U11.B4 v1(28.95,24.34)
  ART03 w0.127: v1(28.95,24.34) 27.69,25.6 27.69,27.18 28.19,27.69 28.19,31.75 27.81,32.13 27.81,35.69 28.32,36.2 28.32,41.15 29.44,42.27 v1(29.44,43.05)
PTB5: length 20.7
  TOP w0.127: v1(30.24,43.05) 30.64,43.45 U2.Y8 ; U11.B3 28.14,24.35 28.14,25.1 28.57,25.53 v1(28.95,25.9)
  ART03 w0.127: v1(28.95,25.9) 28.95,32.89 29.84,33.78 29.84,40.61 30.24,41.01 v1(30.24,43.05)
PTB6: length 24.6
  TOP w0.127: U2.W8 30.64,44.25 v1(30.24,43.85) ; U11.E6 v1(30.55,21.94)
  ART03 w0.127: v1(30.55,21.94) 30.15,22.34 29.58,22.34 29.35,22.57 29.35,22.59 29.35,22.59 29.35,32.78 30.18,33.6 30.18,40.46 30.64,40.93 30.64,43.45 v1(30.24,43.85)
PTB7: length 34.8
  TOP w0.127: U2.D13 34.64,56.25 v1(35.04,55.85) ; v1(29.75,25.14) 28.95,25.14 U11.A3
  ART03 w0.127: v1(29.75,25.14) 30.61,26 30.61,32.51 33.15,35.05 33.15,37.21 33.91,37.97 33.91,42.67 34.64,43.4 34.64,55.45 v1(35.04,55.85)
PTB8: length 33.4
  TOP w0.127: U11.B5 v1(29.75,23.54) ; v1(37.44,52.65) 37.04,52.25 U2.J16
  ART03 w0.127: v1(29.75,23.54) 29.75,24.38 31.92,26.55 31.92,32.55 34.29,34.92 34.29,42.38 36.24,44.32 36.24,46.78 36.58,47.12 36.58,51.79 v1(37.44,52.65)
PTB9: length 34.2
  TOP w0.127: v1(30.55,24.34) 29.75,24.34 U11.A4 ; U2.J19 v1(39.84,51.85)
  ART03 w0.127: v1(39.84,51.85) 39.04,51.05 37.47,51.05 37.04,50.63 37.04,44.4 34.67,42.04 34.67,34.67 32.26,32.26 32.26,26.42 30.55,24.71 v1(30.55,24.34)
PTB10: length 7.8
  TOP w0.127: U2.B15 36.65,58.26 36.65,59.82 37.03,60.2
  TOP w0.152: 37.03,60.2 37.15,60.33 38.35,60.33 38.99,60.96 38.99,62.74 R25.2
PTB15: length 5.5
  TOP w0.127: 35.94,60.2 35.44,59.7 U2.A14
  TOP w0.152: 35.94,60.2 36.96,61.21 R26.2
PTC2: length 11.5
  TOP w0.127: U2.M5 28.24,49.85 v1(27.84,49.45)
  BOTTOM w0.127: 22.86,49.05 27.44,49.05 v1(27.84,49.45)
  BOTTOM w0.152: R28.2 20.19,52.2 20.19,50.55 21.69,49.05 22.86,49.05
